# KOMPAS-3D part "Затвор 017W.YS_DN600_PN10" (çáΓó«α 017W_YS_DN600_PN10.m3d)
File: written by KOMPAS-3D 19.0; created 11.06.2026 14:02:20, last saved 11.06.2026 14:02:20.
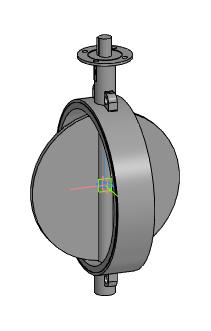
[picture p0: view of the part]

Document properties: Автор: Евгений; Полное имя файла: Z:\3.Личные\kachalov\001_3d для проектировщиков\x.x Тип 017W.Y(S) Затвор дисковый поворотный межфланцевый\_stp_Затвор 017W.YS_DN32-DN1200\Затвор 017W_YS_DN600_PN10.m3d

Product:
- Part/product: Затвор 017W.YS_DN600_PN10

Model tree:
1. Операция без истории:1  (labels: Затвор 017W.YS_DN600_PN10)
